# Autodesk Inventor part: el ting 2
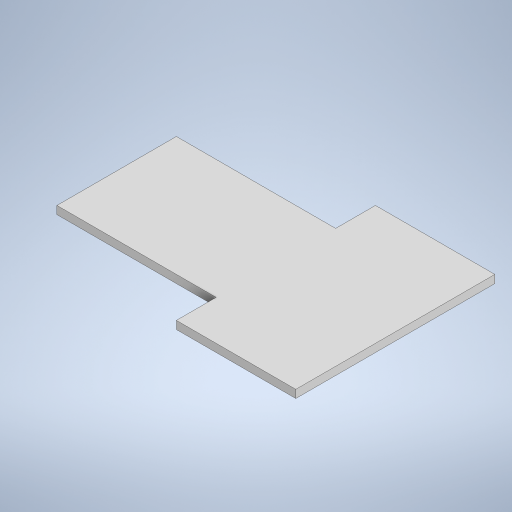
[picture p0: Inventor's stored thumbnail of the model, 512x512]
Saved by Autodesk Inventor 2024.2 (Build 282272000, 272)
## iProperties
Created: 2024-05
Part Number: el ting 2
Material: Generic
Document SubType Name: Modeling
Designer: Karsten
Density: 1 g/cm^3
Appearance: Default
Author: Karsten
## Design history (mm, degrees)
sketch "Sketch1"
  geometry: L1 (0, 0)-(-70, 0); L2 (-70, 0)-(-70, -30); L3 (-70, -30)-(0, -30); L4 (0, -30)-(0, 0); L5 (-70, -30)-(-40, -30); L6 (-40, -30)-(-40, -40); L7 (-40, -40)-(-70, -40); L8 (-70, -40)-(-70, -30); L9 (-70, 0)-(-40, 0); L10 (-40, 0)-(-40, 10); L11 (-40, 10)-(-70, 10); L12 (-70, 10)-(-70, 0); 2 further points
  constraints: 24 end point, 6 parallel, 3 horizontal, 3 perpendicular
  dimensions: "d0" = 70 distance of L3.end L2.end; "d1" = 30 distance of L2.end L1.end; "d2" = 30 distance of L6.end L7.end; "d3" = 10 distance of L5.end L6.end; "d4" = 30 distance of L11.end L10.end; "d5" = 10 distance of L10.end L9.end
extrude "Extrusion1" new body sketch "Sketch1" distance "d6" = 2; taper "d7" = 0 deg
body "Solid1"
